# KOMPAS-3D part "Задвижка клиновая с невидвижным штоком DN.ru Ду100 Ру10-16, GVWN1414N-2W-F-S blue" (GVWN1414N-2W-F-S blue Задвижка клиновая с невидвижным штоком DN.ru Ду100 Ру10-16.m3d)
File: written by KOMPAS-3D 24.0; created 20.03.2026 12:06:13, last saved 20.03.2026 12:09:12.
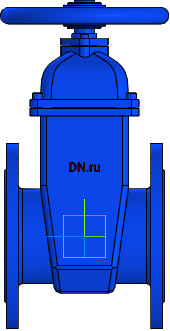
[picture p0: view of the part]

Document properties: Автор: R2D2; Полное имя файла: GVWN1414N-2W-F-S blue Задвижка клиновая с невидвижным штоком DN.ru Ду100 Ру10-16.cdw

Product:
- Part/product: Задвижка клиновая с невидвижным штоком DN.ru Ду100 Ру10-16  | designation GVWN1414N-2W-F-S blue
    Масса: 14
    Раздел спецификации: Прочие изделия
    Форматы листов документа: A2
    Примечание: D040-10582

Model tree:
1. Операция без истории:1

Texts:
  GVWN1414N-2W-F-S blue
